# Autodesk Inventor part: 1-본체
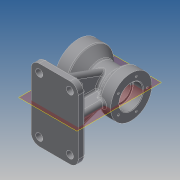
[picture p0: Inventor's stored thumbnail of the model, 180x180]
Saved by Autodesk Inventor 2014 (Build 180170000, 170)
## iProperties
Created: 2015-08
Part Number: 1-본체
Material: Aluminum 6061
Document SubType Name: Modeling
Designer: user
Density: 2.71 g/cm^3
Appearance: Default
Author: user
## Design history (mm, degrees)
sketch "Sketch1"
  geometry: L1 (-45, 0)-(45, 0); L2 (-45, 0)-(-45, 35); L3 (-45, 35)-(-25, 35); L4 (-25, 35)-(-19.804, 26); L5 (-19.804, 26)-(8.315, 26); L6 (8.315, 26)-(25, 40); L7 (25, 40)-(45, 40); L8 (45, 40)-(45, 0); 2 further points
  constraints: 16 end point, 2 horizontal, 1 coincident, 1 midpoint, 1 vertical
  dimensions: "d0" = 90 distance of L1.start L1.end; "d1" = 80 diameter of L7 L1; "d2" = 20 distance of L6.end L7.end; "d3" = 70 diameter of L3 L1; "d4" = 20 distance of L2.end L3.end; "d5" = 120 deg angle of L5 L4; "d6" = 140 deg angle of L6 L5; "d7" = 52 diameter of L5 L1
revolve "Revolution1" sketch "Sketch1" stored, may be unused: angle "d8" = 90 deg
workplane "Work Plane1"
sketch "Sketch2"
  geometry: L1 (-45, -61)-(-45, 61); L2 (-45, -35)-(-45, 35) reference; L3 (-45, 61)-(35, 61); L4 (35, 61)-(35, -61); L5 (35, -61)-(-45, -61); 1 further point
  constraints: 8 end point, 2 midpoint, 1 vertical
  dimensions: "d10" = 122 distance of L1.start L1.end
extrude "Extrusion1" join sketch "Sketch2" distance "d12" = 12; taper "d13" = 0 deg
sketch "Sketch3"
  geometry: L1 (35, -6)-(-25, -6); L2 (-25, -6)-(-25, 6); L3 (-25, 6)-(35, 6); L4 (35, 6)-(35, -6); L5 (35, -6)-(-25, 6); L6 (-25, -6)-(35, 6); 2 further points
  constraints: 12 end point, 2 midpoint
extrude "Extrusion2" join sketch "Sketch3" distance "d14" = 60; taper "d15" = 0 deg
workplane "Work Plane2"
workplane "Work Plane3"
sketch "Sketch10"
  geometry: L1 (70, 50)-(90, 50) reference; L2 (0, 12)-(80, 12) reference; L3 (70, 12)-(76.7, 50); 1 further point
  constraints: 2 end point, 2 point on line
  dimensions: "d112" = 80 deg angle of L2 L3; "d113" = 10 distance of L2.end L3.start
feature "Rib1" sketch "Sketch10" dims "d114" = 1, "d115" = 12, "d116" = 0, "d117" = 0, "d118" = 1, "d119" = 1
sketch "Sketch4"
  geometry: L1 (122, 0)-(0, 0) reference; L2 (0, 0)-(0, 12) reference; L3 (122, 12)-(0, 12) reference; L4 (122, 0)-(122, 12) reference; L5 (10, 12)-(35.909, 83.185); L6 (86.091, 83.185)-(112, 12); L7 (10, 12)-(112, 12); A1 r 26 centre (61, 90) between (67, 64.702) and (55, 64.702) reference; A2 r 26 centre (61, 90) between (35.909, 83.185) and (86.091, 83.185); 1 further point
  constraints: 6 end point, 4 point on circle, 2 point on line, 1 centre point, 1 coincident
  dimensions: "d16" = 70 deg angle of L3 L5; "d17" = 70 deg angle of L3 L6; "d18" = 10 distance of L3.start L6.end; "d19" = 10 distance from line of L5.start L2
extrude "Extrusion3" join sketch "Sketch4" stored distance "d20" = 12; taper "d21" = 0 deg
sketch "Sketch5"
  geometry: L1 (45, -61)-(45, 61) reference; L2 (-35, -61)-(45, -61) reference; 5 further points
  constraints: 2 horizontal alignment, 2 vertical alignment
  dimensions: "d22" = 94 distance of point (-21, -47) point (-21, 47); "d23" = 52 distance of point (31, -47) point (-21, -47); "d24" = 14 distance from line of L1 point (31, -47); "d25" = 14 distance from line of L2 point (-21, -47)
hole "Hole1" sketch "Sketch5" at (-21, 47), (31, 47), (31, -47), (-21, -47) diameter "d26" = 12; stored, may be unused: countersink angle "d30" = 90 deg, drill point angle "d32" = 118 deg; dims "d27" = 6, "d28" = 4, "d29" = 2, "d31" = 8
fillet "Fillet1" dims "d33" = 14, "d34" = 6
fillet "Fillet2" dims "d35" = 3
fillet "Fillet3" dims "d36" = 5
hole "Hole2" diameter "d39" = 40; stored, may be unused: countersink angle "d43" = 90 deg, drill point angle "d45" = 0 deg; dims "d37" = 10, "d38" = 10, "d40" = 6, "d41" = 4, "d42" = 2, "d44" = 17
hole "Hole3" diameter "d48" = 52; stored, may be unused: countersink angle "d52" = 90 deg, drill point angle "d54" = 0 deg; dims "d46" = 10, "d47" = 10, "d49" = 6, "d50" = 4, "d51" = 2, "d53" = 20
hole "Hole4" diameter "d57" = 38; stored, may be unused: countersink angle "d61" = 90 deg, drill point angle "d63" = 0 deg; dims "d55" = 10, "d56" = 10, "d58" = 6, "d59" = 4, "d60" = 2, "d62" = 3
hole "Hole5" diameter "d66" = 32; stored, may be unused: countersink angle "d70" = 90 deg, drill point angle "d72" = 0 deg; dims "d64" = 10, "d65" = 10, "d67" = 6, "d68" = 4, "d69" = 2, "d71" = 3
sketch "Sketch6"
  geometry: C1 r 35 at (0, 0) reference; 2 further points
  constraints: 1 coincident, 1 vertical alignment, 2 other
hole "Hole6" sketch "Sketch6" at (0, 27) diameter "d73" = 3.242; stored, may be unused: countersink angle "d77" = 90 deg, drill point angle "d79" = 118 deg; dims "d74" = 10, "d75" = 4, "d76" = 2, "d78" = 13
pattern_circular "Circular Pattern1" dims angle "d81" = 360 deg
sketch "Sketch7"
  geometry: C1 r 40 at (0, 0) reference; 2 further points
  constraints: 1 coincident, 1 vertical alignment, 2 other
hole "Hole7" sketch "Sketch7" at (0, 33) diameter "d83" = 3.242; stored, may be unused: countersink angle "d87" = 90 deg, drill point angle "d89" = 118 deg; dims "d84" = 10, "d85" = 4, "d86" = 2, "d88" = 13
pattern_circular "Circular Pattern2" dims angle "d91" = 360 deg
fillet "Fillet4" dims "d93" = 0.3, "d94" = 3
chamfer "Chamfer1" distance "d95" = 1; stored, may be unused: second distance "d96" = 2, angle "d97" = 45 deg
sketch "Sketch8"
  geometry: L1 (-13, -3)-(-2, -3) reference; L2 (-6, 0)-(-6, 37) reference; 2 further points
  constraints: 1 other
  dimensions: "d98" = 24 distance from line of L1 point (10, 21); "d99" = 16 distance from line of L2 point (10, 21)
emboss "Emboss1" sketch "Sketch8" dims "d0" = 90, "d1" = 80, "d2" = 20, "d3" = 70, "d4" = 20, "d5" = 120 deg, "d6" = 140 deg, "d7" = 52, "d100" = 0.5, "d101" = 0
sketch "Sketch9"
  geometry: L1 (-85, 30)-(-85, 36); L2 (-79, 30)-(-79, 36); L3 (-91, 36)-(-91, 30); L4 (-14, 12)-(-108, 12) reference; L5 (-37, 30)-(-37, 36); L6 (-31, 30)-(-31, 36); L7 (-43, 36)-(-43, 30); L8 (-85, 33)-(-37, 33); A1 r 6 centre (-85, 30) between (-91, 30) and (-79, 30); A2 r 6 centre (-85, 36) between (-79, 36) and (-91, 36); A3 r 6 centre (-37, 30) between (-43, 30) and (-31, 30); A4 r 6 centre (-37, 36) between (-31, 36) and (-43, 36); 2 further points
  constraints: 18 end point, 8 point on circle, 8 tangent, 4 centre point, 4 midpoint, 2 parallel, 1 horizontal alignment, 1 vertical alignment
  dimensions: "d102" = 12 distance between parallel lines of L2 L3; "d103" = 18 dimension on A2 A1; "d105" = 18 dimension on A3 A4; "d106" = 12 distance between parallel lines of L7 L6; "d107" = 18 distance from line of L4 L1.start; "d108" = 48 distance of L8.start L8.end; "d109" = 18 distance from line of L4 L5.start
extrude "Extrusion4" cut sketch "Sketch9" stored distance "d110" = 60; taper "d111" = 0 deg
fillet "Fillet5" dims "d120" = 6
fillet "Fillet6" dims "d121" = 3
body "Solid1"
node "Projected Loop1"
